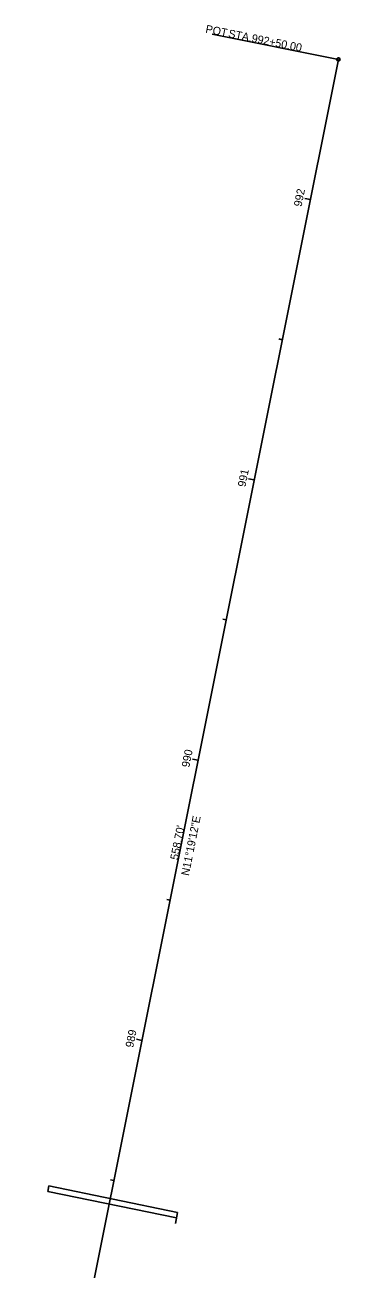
# Model space of a CAD drawing. Extents: x 2227316 to 2230534, y 679272 to 682221.
# Drawn here: x 2228282.4 to 2228392.6, y 680566.5 to 681001.7 of the extents above; entities that cross this region are included whole.
import ezdxf

# ---------------------------------------------------------------- set-up
doc = ezdxf.new("R2010")
doc.units = 0
for name, color, linetype in [('GE_X_Alignment', 7, 'Continuous'), ('GE_X_Alignment_100_Bearings', 7, 'Continuous'), ('GE_X_Alignment_100_Cardinal_Points', 7, 'Continuous'), ('GE_X_Alignment_100_Distances', 7, 'Continuous'), ('GE_X_Alignment_100_Stations', 7, 'Continuous'), ('SC_Scratch1', 7, 'Continuous'), ('SC_Scratch3', 7, 'Continuous')]:
    doc.layers.add(name, color=color, linetype=linetype)

msp = doc.modelspace()

# ---------------------------------------------------------------- linework, layer by layer
at = {"layer": 'GE_X_Alignment'}
msp.add_line((2228282.37, 680441.81), (2228392.03, 680989.64), dxfattribs=at)
at = {"layer": 'GE_X_Alignment_100_Cardinal_Points'}
msp.add_line((2228392.03, 680989.64), (2228347.91, 680998.48), dxfattribs=at)
msp.add_circle((2228392.03, 680989.64), 0.6, dxfattribs=at)
at = {"layer": 'GE_X_Alignment_100_Stations'}
for p, q in [((2228382.22, 680940.62), (2228380.26, 680941.01)), ((2228372.41, 680891.59), (2228371.23, 680891.83)), ((2228362.59, 680842.57), (2228360.63, 680842.96)), ((2228352.78, 680793.54), (2228351.6, 680793.77)), ((2228342.96, 680744.51), (2228341, 680744.9)), ((2228333.15, 680695.48), (2228331.97, 680695.72)), ((2228323.33, 680646.46), (2228321.37, 680646.85)), ((2228313.52, 680597.43), (2228312.34, 680597.66))]:
    msp.add_line(p, q, dxfattribs=at)
at = {"layer": 'SC_Scratch1'}
msp.add_line((2228282.37, 680441.81), (2228392.03, 680989.64), dxfattribs=at)
at = {"layer": 'SC_Scratch3'}
for p, q in [((2228290.77, 680595.58), (2228290.39, 680593.61)), ((2228335.42, 680584.34), (2228290.39, 680593.61)), ((2228335.8, 680586.3), (2228290.73, 680595.58)), ((2228335.8, 680586.3), (2228335.04, 680582.37))]:
    msp.add_line(p, q, dxfattribs=at)

# ---------------------------------------------------------------- texts
at = {"layer": 'GE_X_Alignment_100_Bearings'}
msp.add_text('N11°19\'12"E', height=2.8, rotation=78.68, dxfattribs=at).set_placement((2228339.73, 680703.89))
at = {"layer": 'GE_X_Alignment_100_Cardinal_Points'}
for s, p in [('POT', (2228345.37, 680999.02)), (' STA. ', (2228352.36, 680997.62)), ('992+50.00', (2228361.5, 680995.79))]:
    msp.add_text(s, height=2.8, rotation=348.68, dxfattribs=at).set_placement(p)
at = {"layer": 'GE_X_Alignment_100_Distances'}
msp.add_text("558.70'", height=2.8, rotation=78.68, dxfattribs=at).set_placement((2228335.9, 680709.42))
at = {"layer": 'GE_X_Alignment_100_Stations'}
for s, p in [('992', (2228379.14, 680937.96)), ('991', (2228359.51, 680839.9)), ('990', (2228339.87, 680741.8)), ('989', (2228320.25, 680643.78))]:
    msp.add_text(s, height=2.8, rotation=78.68, dxfattribs=at).set_placement(p)

doc.saveas('drawing.dxf')
